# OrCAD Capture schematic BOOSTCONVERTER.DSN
size A
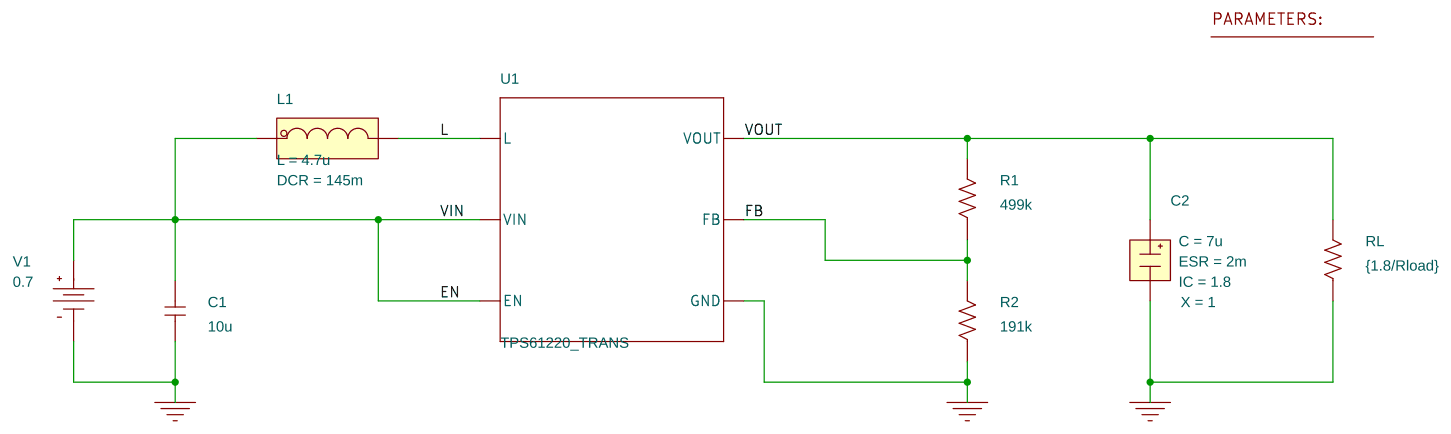
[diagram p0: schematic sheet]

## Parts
1  PARAM
C1  10u  [RAD/CK05]
C2  CESR
L1  LDCR
R1  499k  [AX/RC05]
R2  191k  [AX/RC05]
RL  {1.8/Rload}  [AX/RC05]
U1  TPS61220_TRANS
V1  VDC

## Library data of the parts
1 = PARAM: Rload: 20m
C1 = C
C2 = CESR: C: 7u; ESR: 2m; IC: 1.8; PSpiceTemplate: X^@REFDES %IN %OUT @MODEL PARAMS:  ?C|C=@C||C=100u|  ?ESR|ESR=@ESR||ESR=0.01| ?X|X=@X||X=2|  ?IC|IC=@IC||IC=2|; X: 1
L1 = LDCR: DCR: 145m; IC: 0; L: 4.7u; PSpiceTemplate: X^@REFDES %IN %OUT @MODEL PARAMS:  ?L|L=@L||L=1u|  ?DCR|DCR=@DCR||DCR=0.01| ?IC|IC=@IC||IC=0|
R1 R2 RL = R
U1 = TPS61220_TRANS
V1 = VDC: DC: 0.7

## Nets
0: C1.2 C2.3(OUT) R2.1 RL.1 U1.GND V1.1(-)
EN: C1.1 L1.1(IN) U1.EN U1.VIN V1.0(+)
FB: R1.1 R2.2 U1.FB
L: L1.3(OUT) U1.L
VOUT: C2.1(IN) R1.2 RL.2 U1.VOUT
